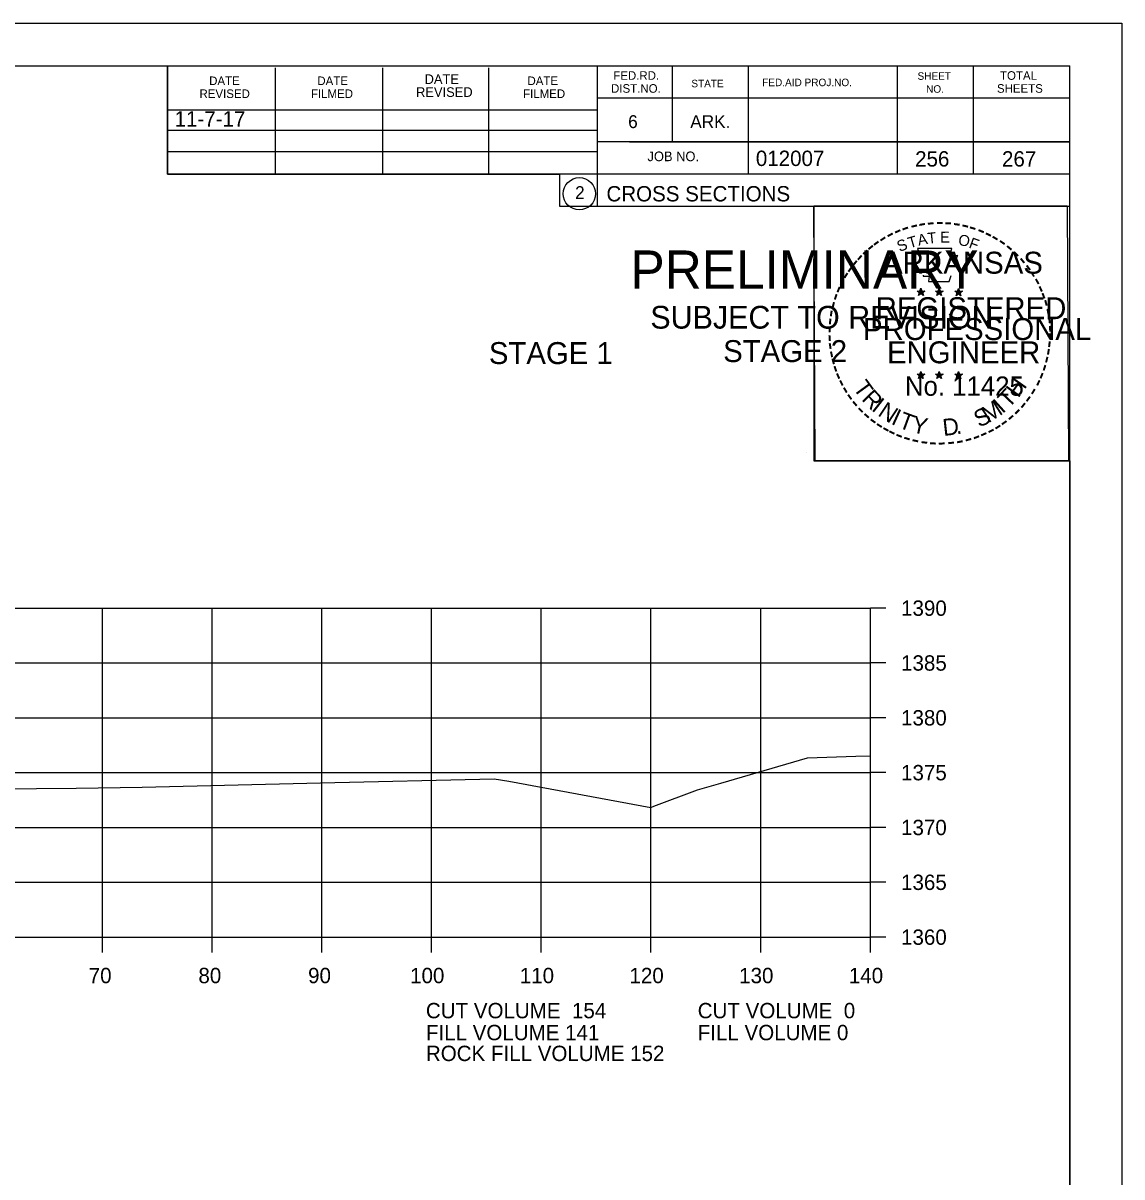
# Model space of a CAD drawing. Extents: x 1374311 to 1383814, y 384102 to 406278.
# Drawn here: x 1382783.6 to 1382883.8, y 385654 to 385759.2 of the extents above; entities that cross this region are included whole.
import ezdxf

# ---------------------------------------------------------------- set-up
doc = ezdxf.new("R2010")
doc.units = 0
for name, color, linetype in [('R_Axis', 7, 'Continuous'), ('R_Axis Annot', 7, 'Continuous'), ('R_Border', 7, 'Continuous'), ('R_Border PE', 7, 'Continuous'), ('R_Border Prem', 7, 'Continuous'), ('R_Exist Surface', 7, 'Continuous'), ('R_Fin Surface', 7, 'Continuous'), ('R_Grid', 7, 'Continuous'), ('R_No Plot', 7, 'Continuous'), ('R_Water', 7, 'Continuous')]:
    doc.layers.add(name, color=color, linetype=linetype)

msp = doc.modelspace()

# ---------------------------------------------------------------- linework, layer by layer
at = {"layer": 'R_Axis'}
for p, q in [((1382860.86, 385675.89), (1382860.86, 385705.89)), ((1382862.26, 385705.89), (1382860.86, 385705.89)), ((1382862.26, 385700.89), (1382860.86, 385700.89)), ((1382862.26, 385695.89), (1382860.86, 385695.89)), ((1382862.26, 385690.89), (1382860.86, 385690.89)), ((1382862.26, 385685.89), (1382860.86, 385685.89)), ((1382862.26, 385680.89), (1382860.86, 385680.89)), ((1382580.86, 385675.89), (1382860.86, 385675.89)), ((1382790.86, 385674.49), (1382790.86, 385675.89)), ((1382800.86, 385674.49), (1382800.86, 385675.89)), ((1382810.86, 385674.49), (1382810.86, 385675.89)), ((1382820.86, 385674.49), (1382820.86, 385675.89)), ((1382830.86, 385674.49), (1382830.86, 385675.89)), ((1382840.86, 385674.49), (1382840.86, 385675.89)), ((1382850.86, 385674.49), (1382850.86, 385675.89)), ((1382860.86, 385674.49), (1382860.86, 385675.89)), ((1382862.26, 385675.89), (1382860.86, 385675.89))]:
    msp.add_line(p, q, dxfattribs=at)
at = {"layer": 'R_Border'}
for p, q in [((1382562.86, 385755.35), (1382879.04, 385755.35)), ((1382796.78, 385745.47), (1382796.78, 385755.35)), ((1382806.64, 385745.47), (1382806.64, 385755.15)), ((1382816.4, 385745.47), (1382816.4, 385755.15)), ((1382826.08, 385745.47), (1382826.08, 385755.15)), ((1382835.94, 385755.35), (1382835.94, 385742.55)), ((1382842.78, 385755.35), (1382842.78, 385748.41)), ((1382849.72, 385755.35), (1382849.72, 385745.47)), ((1382863.3, 385755.35), (1382863.3, 385745.47)), ((1382870.24, 385755.35), (1382870.24, 385745.47)), ((1382879.04, 385549.89), (1382879.04, 385755.35)), ((1382879.04, 385752.41), (1382835.94, 385752.41)), ((1382879.04, 385752.43), (1382879.04, 385752.43)), ((1382796.78, 385751.33), (1382835.94, 385751.33)), ((1382796.78, 385749.47), (1382835.94, 385749.47)), ((1382879.04, 385748.41), (1382835.94, 385748.41)), ((1382838.9, 385748.41), (1382879.04, 385748.41)), ((1382796.78, 385745.47), (1382796.78, 385747.53)), ((1382796.78, 385747.53), (1382835.94, 385747.53)), ((1382879.04, 385745.47), (1382796.78, 385745.47)), ((1382835.94, 385742.55), (1382879.04, 385742.55))]:
    msp.add_line(p, q, dxfattribs=at)
msp.add_circle((1382834.33, 385743.68), 1.47, dxfattribs=at)
at = {"layer": 'R_Border PE'}
for p, q in [((1382865.47, 385735.06), (1382865.43, 385734.81)), ((1382865.47, 385734.69), (1382865.47, 385735.06)), ((1382865.47, 385735.06), (1382865.52, 385734.81)), ((1382867.14, 385735.06), (1382867.1, 385734.81)), ((1382867.14, 385734.69), (1382867.14, 385735.06)), ((1382867.14, 385735.06), (1382867.19, 385734.81)), ((1382868.91, 385735.05), (1382868.87, 385734.79)), ((1382868.91, 385734.68), (1382868.91, 385735.05)), ((1382868.91, 385735.05), (1382868.96, 385734.8)), ((1382865.13, 385734.8), (1382865.47, 385734.69)), ((1382865.13, 385734.8), (1382865.38, 385734.76)), ((1382865.13, 385734.8), (1382865.36, 385734.68)), ((1382865.26, 385734.4), (1382865.47, 385734.69)), ((1382865.26, 385734.4), (1382865.38, 385734.64)), ((1382865.26, 385734.4), (1382865.47, 385734.61)), ((1382865.82, 385734.8), (1382865.47, 385734.69)), ((1382865.69, 385734.4), (1382865.47, 385734.69)), ((1382865.69, 385734.4), (1382865.47, 385734.61)), ((1382865.82, 385734.8), (1382865.54, 385734.75)), ((1382865.69, 385734.4), (1382865.55, 385734.69)), ((1382865.82, 385734.8), (1382865.62, 385734.7)), ((1382866.8, 385734.8), (1382867.14, 385734.69)), ((1382866.8, 385734.8), (1382867.05, 385734.76)), ((1382866.8, 385734.8), (1382867.03, 385734.68)), ((1382866.93, 385734.4), (1382867.14, 385734.69)), ((1382866.93, 385734.4), (1382867.05, 385734.64)), ((1382866.93, 385734.4), (1382867.14, 385734.61)), ((1382867.49, 385734.8), (1382867.14, 385734.69)), ((1382867.36, 385734.4), (1382867.14, 385734.69)), ((1382867.36, 385734.4), (1382867.14, 385734.61)), ((1382867.49, 385734.8), (1382867.21, 385734.75)), ((1382867.36, 385734.4), (1382867.22, 385734.69)), ((1382867.49, 385734.8), (1382867.29, 385734.7)), ((1382868.56, 385734.79), (1382868.91, 385734.68)), ((1382868.56, 385734.79), (1382868.81, 385734.75)), ((1382868.56, 385734.79), (1382868.8, 385734.67)), ((1382868.69, 385734.38), (1382868.91, 385734.68)), ((1382868.69, 385734.38), (1382868.82, 385734.63)), ((1382868.69, 385734.38), (1382868.91, 385734.6)), ((1382869.26, 385734.79), (1382868.91, 385734.68)), ((1382869.12, 385734.38), (1382868.91, 385734.68)), ((1382869.12, 385734.38), (1382868.91, 385734.6)), ((1382869.26, 385734.79), (1382868.97, 385734.74)), ((1382869.12, 385734.38), (1382868.98, 385734.67)), ((1382869.26, 385734.79), (1382869.05, 385734.69)), ((1382865.12, 385727.23), (1382865.47, 385727.12)), ((1382865.12, 385727.23), (1382865.37, 385727.19)), ((1382865.12, 385727.23), (1382865.36, 385727.11)), ((1382865.25, 385726.82), (1382865.47, 385727.12)), ((1382865.25, 385726.82), (1382865.38, 385727.07)), ((1382865.25, 385726.82), (1382865.47, 385727.04)), ((1382865.47, 385727.48), (1382865.43, 385727.23)), ((1382865.47, 385727.12), (1382865.47, 385727.48)), ((1382865.47, 385727.48), (1382865.52, 385727.23)), ((1382865.82, 385727.23), (1382865.47, 385727.12)), ((1382865.68, 385726.82), (1382865.47, 385727.12)), ((1382865.68, 385726.82), (1382865.47, 385727.04)), ((1382865.82, 385727.23), (1382865.53, 385727.18)), ((1382865.68, 385726.82), (1382865.55, 385727.11)), ((1382865.82, 385727.23), (1382865.61, 385727.13)), ((1382866.79, 385727.23), (1382867.14, 385727.12)), ((1382866.79, 385727.23), (1382867.04, 385727.19)), ((1382866.79, 385727.23), (1382867.03, 385727.11)), ((1382866.92, 385726.82), (1382867.14, 385727.12)), ((1382866.92, 385726.82), (1382867.05, 385727.07)), ((1382866.92, 385726.82), (1382867.14, 385727.04)), ((1382867.14, 385727.48), (1382867.1, 385727.23)), ((1382867.14, 385727.12), (1382867.14, 385727.48)), ((1382867.14, 385727.48), (1382867.19, 385727.23)), ((1382867.49, 385727.23), (1382867.14, 385727.12)), ((1382867.35, 385726.82), (1382867.14, 385727.12)), ((1382867.35, 385726.82), (1382867.14, 385727.04)), ((1382867.49, 385727.23), (1382867.2, 385727.18)), ((1382867.35, 385726.82), (1382867.22, 385727.11)), ((1382867.49, 385727.23), (1382867.28, 385727.13)), ((1382868.56, 385727.22), (1382868.91, 385727.11)), ((1382868.56, 385727.22), (1382868.81, 385727.18)), ((1382868.56, 385727.22), (1382868.79, 385727.1)), ((1382868.69, 385726.81), (1382868.91, 385727.11)), ((1382868.69, 385726.81), (1382868.82, 385727.06)), ((1382868.69, 385726.81), (1382868.9, 385727.03)), ((1382868.91, 385727.47), (1382868.87, 385727.22)), ((1382869.12, 385726.81), (1382868.9, 385727.03)), ((1382868.91, 385727.11), (1382868.91, 385727.47)), ((1382868.91, 385727.47), (1382868.96, 385727.22)), ((1382869.25, 385727.22), (1382868.91, 385727.11)), ((1382869.12, 385726.81), (1382868.91, 385727.11)), ((1382869.25, 385727.22), (1382868.97, 385727.17)), ((1382869.12, 385726.81), (1382868.98, 385727.1)), ((1382869.25, 385727.22), (1382869.05, 385727.12))]:
    msp.add_line(p, q, dxfattribs=at)
for points in [[(1382865.17, 385738.68), (1382865.44, 385737.85)], [(1382868.68, 385737.76), (1382868.82, 385738.04), (1382868.13, 385738.02), (1382868.28, 385738.68), (1382865.17, 385738.68)], [(1382865.66, 385736.26), (1382865.66, 385736.17), (1382866.22, 385736.15), (1382866.17, 385735.68), (1382868.04, 385735.68), (1382868.24, 385736.22)], [(1382865.47, 385735.06), (1382865.69, 385734.4), (1382865.13, 385734.8), (1382865.82, 385734.8), (1382865.26, 385734.4), (1382865.47, 385735.06)], [(1382867.14, 385735.06), (1382867.36, 385734.4), (1382866.8, 385734.8), (1382867.49, 385734.8), (1382866.93, 385734.4), (1382867.14, 385735.06)], [(1382868.91, 385735.05), (1382869.12, 385734.38), (1382868.56, 385734.79), (1382869.26, 385734.79), (1382868.69, 385734.38), (1382868.91, 385735.05)], [(1382865.47, 385727.48), (1382865.68, 385726.82), (1382865.12, 385727.23), (1382865.82, 385727.23), (1382865.25, 385726.82), (1382865.47, 385727.48)], [(1382867.14, 385727.48), (1382867.35, 385726.82), (1382866.79, 385727.23), (1382867.49, 385727.23), (1382866.92, 385726.82), (1382867.14, 385727.48)], [(1382868.91, 385727.47), (1382869.12, 385726.81), (1382868.56, 385727.22), (1382869.25, 385727.22), (1382868.69, 385726.81), (1382868.91, 385727.47)]]:
    msp.add_lwpolyline(points, dxfattribs=at)
for centre, radius in [((1382865.47, 385734.69), 0.172), ((1382865.47, 385734.69), 0.145), ((1382865.47, 385734.69), 0.116), ((1382865.47, 385734.69), 0.0991), ((1382865.47, 385734.69), 0.0747), ((1382865.47, 385734.69), 0.0495), ((1382865.47, 385734.69), 0.0296), ((1382867.14, 385734.69), 0.172), ((1382867.14, 385734.69), 0.145), ((1382867.14, 385734.69), 0.116), ((1382867.14, 385734.69), 0.0991), ((1382867.14, 385734.69), 0.0747), ((1382867.14, 385734.69), 0.0495), ((1382867.14, 385734.69), 0.0296), ((1382868.91, 385734.68), 0.172), ((1382868.91, 385734.68), 0.145), ((1382868.91, 385734.68), 0.116), ((1382868.91, 385734.68), 0.0991), ((1382868.91, 385734.68), 0.0747), ((1382868.91, 385734.68), 0.0495), ((1382868.91, 385734.68), 0.0296), ((1382865.47, 385727.12), 0.172), ((1382865.47, 385727.12), 0.145), ((1382865.47, 385727.12), 0.116), ((1382865.47, 385727.12), 0.0991), ((1382865.47, 385727.12), 0.0747), ((1382865.47, 385727.12), 0.0495), ((1382865.47, 385727.12), 0.0296), ((1382867.14, 385727.12), 0.172), ((1382867.14, 385727.12), 0.145), ((1382867.14, 385727.12), 0.116), ((1382867.14, 385727.12), 0.0991), ((1382867.14, 385727.12), 0.0747), ((1382867.14, 385727.12), 0.0495), ((1382867.14, 385727.12), 0.0296), ((1382868.91, 385727.11), 0.172), ((1382868.91, 385727.11), 0.145), ((1382868.91, 385727.11), 0.116), ((1382868.91, 385727.11), 0.0991), ((1382868.91, 385727.11), 0.0747), ((1382868.91, 385727.11), 0.0495), ((1382868.91, 385727.11), 0.0296)]:
    msp.add_circle(centre, radius, dxfattribs=at)
at = {"layer": 'R_Exist Surface'}
msp.add_lwpolyline([(1382671.67, 385688.5), (1382706.96, 385688.71), (1382707.01, 385688.71), (1382707.07, 385688.71), (1382707.25, 385688.71), (1382707.4, 385688.71), (1382731.28, 385688.95), (1382759.66, 385689.22), (1382761.3, 385689.24), (1382763.19, 385689.26), (1382788.46, 385689.47), (1382794.48, 385689.56), (1382810.72, 385689.95), (1382826.55, 385690.34), (1382827.9, 385690.1), (1382840.86, 385687.72), (1382841.13, 385687.83), (1382845.1, 385689.33), (1382847.24, 385689.94), (1382855.13, 385692.24), (1382859.55, 385692.38), (1382860.86, 385692.42)], dxfattribs=at)
at = {"layer": 'R_Grid'}
for p, q in [((1382580.86, 385705.89), (1382860.86, 385705.89)), ((1382790.86, 385675.89), (1382790.86, 385705.89)), ((1382800.86, 385675.89), (1382800.86, 385705.89)), ((1382810.86, 385675.89), (1382810.86, 385705.89)), ((1382820.86, 385675.89), (1382820.86, 385705.89)), ((1382830.86, 385675.89), (1382830.86, 385705.89)), ((1382840.86, 385675.89), (1382840.86, 385705.89)), ((1382850.86, 385675.89), (1382850.86, 385705.89)), ((1382860.86, 385675.89), (1382860.86, 385705.89)), ((1382580.86, 385700.89), (1382860.86, 385700.89)), ((1382580.86, 385695.89), (1382860.86, 385695.89)), ((1382580.86, 385690.89), (1382860.86, 385690.89)), ((1382580.86, 385685.89), (1382860.86, 385685.89)), ((1382580.86, 385680.89), (1382860.86, 385680.89)), ((1382580.86, 385675.89), (1382860.86, 385675.89))]:
    msp.add_line(p, q, dxfattribs=at)
at = {"layer": 'R_No Plot'}
for p, q in [((1382550.46, 385759.24), (1382883.79, 385759.24)), ((1382855.08, 385720.09), (1382855.08, 385720.09))]:
    msp.add_line(p, q, dxfattribs=at)
for points in [[(1382550.45, 385759.24), (1382883.79, 385759.24), (1382883.79, 385545.91), (1382550.45, 385545.91)], [(1382796.78, 385755.35), (1382796.78, 385745.47), (1382832.51, 385745.47), (1382832.51, 385742.55), (1382855.71, 385742.55), (1382855.71, 385719.33), (1382879.04, 385719.33), (1382879.04, 385549.89), (1382562.86, 385549.89), (1382562.86, 385755.35)], [(1382855.71, 385742.58), (1382878.81, 385742.58), (1382878.93, 385719.33), (1382855.83, 385719.33)]]:
    msp.add_lwpolyline(points, close=True, dxfattribs=at)

# ---------------------------------------------------------------- texts
at = {"layer": 'R_Axis Annot'}
for s, p in [('1390', (1382863.66, 385705.19)), ('1385', (1382863.66, 385700.19)), ('1380', (1382863.66, 385695.19)), ('1375', (1382863.66, 385690.19)), ('1370', (1382863.66, 385685.19)), ('1365', (1382863.66, 385680.19)), ('1360', (1382863.66, 385675.19)), ('70', (1382789.6, 385671.69)), ('80', (1382799.6, 385671.69)), ('90', (1382809.6, 385671.69)), ('100', (1382818.9, 385671.69)), ('110', (1382828.9, 385671.69)), ('120', (1382838.9, 385671.69)), ('130', (1382848.9, 385671.69)), ('140', (1382858.9, 385671.69)), ('CUT VOLUME  154', (1382820.34, 385668.49)), ('CUT VOLUME  0', (1382845.12, 385668.49)), ('FILL VOLUME 141', (1382820.34, 385666.49)), ('FILL VOLUME 0', (1382845.12, 385666.49)), ('ROCK FILL VOLUME 152', (1382820.34, 385664.59))]:
    msp.add_text(s, height=1.4, dxfattribs=at).set_placement(p)
at = {"layer": 'R_Border'}
for s, height, p in [('DATE', 0.782, (1382800.58, 385753.59)), ('DATE', 0.782, (1382810.44, 385753.59)), ('DATE', 0.879, (1382820.22, 385753.69)), ('DATE', 0.782, (1382829.6, 385753.59)), ('FED.RD.', 0.782, (1382837.42, 385754.07)), ('STATE', 0.684, (1382844.54, 385753.39)), ('FED.AID PROJ.NO.', 0.684, (1382851, 385753.49)), ('SHEET', 0.684, (1382865.16, 385754.07)), ('TOTAL', 0.782, (1382872.68, 385754.07)), ('REVISED', 0.782, (1382799.7, 385752.41)), ('FILMED', 0.782, (1382809.86, 385752.41)), ('REVISED', 0.879, (1382819.44, 385752.51)), ('FILMED', 0.782, (1382829.2, 385752.41)), ('DIST.NO.', 0.782, (1382837.22, 385752.89)), ('NO.', 0.684, (1382865.94, 385752.89)), ('SHEETS', 0.782, (1382872.4, 385752.89)), ('6', 1.17, (1382838.78, 385749.67)), ('ARK.', 1.172, (1382844.44, 385749.67)), ('012007', 1.4, (1382850.42, 385746.21)), ('JOB NO.', 0.879, (1382840.54, 385746.65)), ('2', 1.17, (1382833.94, 385743.2)), ('CROSS SECTIONS', 1.4, (1382836.8, 385742.98))]:
    msp.add_text(s, height=height, rotation=360, dxfattribs=at).set_placement(p)
at = {"layer": 'R_Border PE'}
for s, height, rotation, p in [('-', 1.6, 24.3072, (1382863.28, 385739.54)), ('-', 1.6, 19.1761, (1382863.91, 385739.81)), ('-', 1.6, 13.6301, (1382864.66, 385740.05)), ('-', 1.6, 10.2193, (1382865.34, 385740.21)), ('-', 1.6, 5.8968, (1382866.07, 385740.32)), ('-', 1.6, 0.1862, (1382866.84, 385740.39)), ('E', 1, 0.8323, (1382867.22, 385739.22)), ('-', 1.6, 357.743, (1382867.57, 385740.38)), ('-', 1.6, 352.1617, (1382868.31, 385740.32)), ('-', 1.6, 347.2049, (1382869.03, 385740.21)), ('-', 1.6, 342.3362, (1382869.66, 385740.06)), ('-', 1.6, 337.8551, (1382870.4, 385739.83)), ('-', 1.6, 36.2317, (1382861.47, 385738.46)), ('-', 1.6, 34.0636, (1382862.05, 385738.85)), ('-', 1.6, 28.7918, (1382862.65, 385739.22)), ('S', 1, 21.594, (1382863.52, 385738.36)), ('T', 1, 16.4036, (1382864.44, 385738.69)), ('A', 1, 11.2132, (1382865.26, 385738.94)), ('T', 1, 6.0228, (1382866.11, 385739.11)), ('O', 1, 350.4515, (1382868.82, 385739.01)), ('F', 1, 340.0707, (1382869.77, 385738.78)), ('-', 1.6, 334.1211, (1382871.03, 385739.56)), ('-', 1.6, 329.6409, (1382871.61, 385739.28)), ('-', 1.6, 325.8627, (1382872.25, 385738.92)), ('-', 1.6, 48.423, (1382860.12, 385737.18)), ('-', 1.6, 42.9622, (1382860.56, 385737.66)), ('-', 1.6, 38.9507, (1382861, 385738.08)), ('ARKANSAS', 2, 360, (1382862.02, 385736.39)), ('-', 1.6, 320.5297, (1382872.86, 385738.49)), ('-', 1.6, 315.5786, (1382873.46, 385738)), ('-', 1.6, 50.6142, (1382859.71, 385736.7)), ('-', 1.6, 309.8797, (1382874.03, 385737.45)), ('-', 1.6, 306.6522, (1382874.56, 385736.85)), ('-', 1.6, 58.0706, (1382858.97, 385735.6)), ('-', 1.6, 54.2325, (1382859.3, 385736.13)), ('-', 1.4, 303.6753, (1382875.04, 385736.28)), ('-', 1.6, 67.7743, (1382858.4, 385734.38)), ('-', 1.6, 62.8713, (1382858.66, 385734.99)), ('-', 1.6, 299.6684, (1382875.36, 385735.68)), ('-', 1.6, 294.6628, (1382875.68, 385735.06)), ('-', 1.6, 72.3945, (1382858.18, 385733.75)), ('REGISTERED', 2, 360, (1382861.34, 385732.24)), ('DWB', 0.01, 360, (1382865.46, 385734.69)), ('DWB', 0.01, 360, (1382867.13, 385734.69)), ('DWB', 0.01, 360, (1382868.9, 385734.68)), ('-', 1.6, 290.5728, (1382875.94, 385734.49)), ('-', 1.6, 285.1233, (1382876.18, 385733.91)), ('-', 1.6, 81.2013, (1382857.85, 385732.32)), ('-', 1.6, 75.461, (1382857.99, 385733.04)), ('-', 1.6, 280.5493, (1382876.38, 385733.17)), ('-', 1.6, 85.1863, (1382857.78, 385731.63)), ('PROFESSIONAL', 2, 360, (1382860.19, 385730.34)), ('-', 1.6, 276.5962, (1382876.54, 385732.4)), ('-', 1.6, 94.1959, (1382857.79, 385730.21)), ('-', 1.6, 89.0622, (1382857.75, 385730.93)), ('-', 1.6, 274.3301, (1382876.6, 385731.68)), ('-', 1.6, 269.9407, (1382876.63, 385731.04)), ('-', 1.6, 98.9479, (1382857.86, 385729.54)), ('ENGINEER', 2, 360, (1382862.38, 385728.22)), ('-', 1.6, 263.5172, (1382876.61, 385730.38)), ('-', 1.6, 101.7149, (1382858, 385728.81)), ('-', 1.6, 105.4578, (1382858.16, 385728.21)), ('-', 1.6, 255.7626, (1382876.43, 385729.05)), ('-', 1.6, 260.9953, (1382876.54, 385729.72)), ('-', 1.6, 109.0874, (1382858.37, 385727.58)), ('-', 1.6, 252.8681, (1382876.25, 385728.33)), ('-', 1.6, 114.0643, (1382858.63, 385726.98)), ('-', 1.6, 115.7289, (1382858.93, 385726.37)), ('T', 1.54, 306.0406, (1382859.23, 385725.96)), ('No. 11425', 1.757, 360, (1382864.01, 385725.26)), ('DWB', 0.01, 360, (1382865.46, 385727.11)), ('DWB', 0.01, 360, (1382867.13, 385727.12)), ('DWB', 0.01, 360, (1382868.89, 385727.11)), ('H', 1.54, 54.6088, (1382874.35, 385724.99)), ('-', 1.6, 244.6197, (1382875.77, 385727.02)), ('-', 1.6, 247.8887, (1382876.03, 385727.65)), ('-', 1.6, 120.4471, (1382859.29, 385725.78)), ('R', 1.54, 314.005, (1382859.99, 385724.91)), ('T', 1.54, 46.6444, (1382873.46, 385724.05)), ('-', 1.6, 239.0712, (1382875.37, 385726.27)), ('-', 1.6, 125.8934, (1382859.69, 385725.22)), ('-', 1.6, 130.7181, (1382860.15, 385724.67)), ('I', 1.54, 321.9694, (1382860.89, 385723.98)), ('N', 1.54, 326.5002, (1382861.46, 385723.51)), ('M', 1.54, 32.6563, (1382871.61, 385722.73)), ('I', 1.54, 42.1136, (1382872.9, 385723.57)), ('-', 1.6, 231.2538, (1382874.54, 385725.05)), ('-', 1.6, 233.8452, (1382874.97, 385725.62)), ('-', 1.6, 134.2238, (1382860.67, 385724.12)), ('-', 1.6, 138.9338, (1382861.2, 385723.66)), ('I', 1.54, 335.3603, (1382862.67, 385722.72)), ('T', 1.54, 339.8912, (1382863.33, 385722.39)), ('Y', 1.54, 347.8556, (1382864.55, 385721.95)), ('S', 1.54, 26.9312, (1382870.78, 385722.32)), ('-', 1.6, 221.0851, (1382873.54, 385723.98)), ('-', 1.6, 225.7653, (1382874.06, 385724.49)), ('-', 1.6, 144.6463, (1382861.75, 385723.25)), ('-', 1.6, 148.0898, (1382862.31, 385722.88)), ('-', 1.6, 151.5704, (1382862.89, 385722.56)), ('D', 1.54, 6.3969, (1382867.53, 385721.59)), ('-', 1.6, 212.2491, (1382872.46, 385723.12)), ('-', 1.6, 215.7363, (1382872.99, 385723.51)), ('-', 1.6, 154.6002, (1382863.41, 385722.31)), ('-', 1.6, 158.5612, (1382864.04, 385722.05)), ('-', 1.6, 162.7983, (1382864.72, 385721.84)), ('-', 1.6, 167.5555, (1382865.44, 385721.68)), ('.', 1.54, 13.7642, (1382868.72, 385721.72)), ('-', 1.6, 195.4743, (1382869.98, 385721.94)), ('-', 1.6, 200.7184, (1382870.65, 385722.18)), ('-', 1.6, 204.2516, (1382871.27, 385722.46)), ('-', 1.6, 207.3568, (1382871.9, 385722.77)), ('-', 1.6, 173.1155, (1382866.21, 385721.57)), ('-', 1.6, 176.5183, (1382866.96, 385721.51)), ('-', 1.6, 181.5918, (1382867.7, 385721.53)), ('-', 1.6, 185.8167, (1382868.51, 385721.61)), ('-', 1.6, 191.2858, (1382869.25, 385721.74))]:
    msp.add_text(s, height=height, rotation=rotation, dxfattribs=at).set_placement(p)
at = {"layer": 'R_Border Prem'}
for s, height, p in [('PRELIMINARY', 3.5, (1382838.99, 385735.01)), ('DWB', 0.01, (1382839.74, 385736.86)), ('SUBJECT TO REVISION', 2.0751, (1382840.8, 385731.38))]:
    msp.add_text(s, height=height, rotation=360, dxfattribs=at).set_placement(p)
at = {"layer": 'R_Fin Surface'}
msp.add_text('11-7-17', height=1.4, dxfattribs=at).set_placement((1382797.43, 385749.81))
at = {"layer": 'R_Water'}
for s, p in [('256', (1382864.94, 385746.16)), ('267', (1382872.86, 385746.16))]:
    msp.add_text(s, height=1.4, rotation=360, dxfattribs=at).set_placement(p)
for s, p in [('STAGE 1', (1382826.08, 385728.15)), ('STAGE 2', (1382847.44, 385728.33))]:
    msp.add_text(s, height=2, dxfattribs=at).set_placement(p)

doc.saveas('drawing.dxf')
